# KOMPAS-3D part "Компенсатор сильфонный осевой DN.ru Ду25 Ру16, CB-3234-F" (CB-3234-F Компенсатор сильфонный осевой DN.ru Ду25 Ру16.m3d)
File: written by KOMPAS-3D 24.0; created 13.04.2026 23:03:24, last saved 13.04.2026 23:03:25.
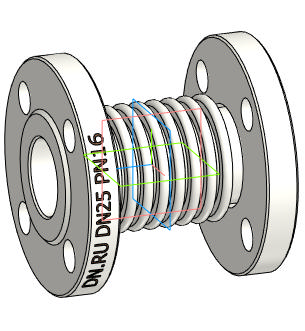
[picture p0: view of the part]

Document properties: Автор: DN.RU; Полное имя файла: D:\PROJECT CAD\DN.RU\...198(ACTUALE). CB-3234-F Компенсатор сильфонный осевой DN.ru\Исходники\DN25\CB-3234-F Компенсатор сильфонный осевой DN.ru Ду25 Ру16.m3d

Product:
- Body: Твердое тело1  | qty 1
    Масса: 2.406826
- Part/product: Компенсатор сильфонный осевой DN.ru Ду25 Ру16  | designation CB-3234-F
    Масса: 2.7
    Раздел спецификации: Прочие изделия
    Комментарий: D140-02110
    Примечание: D140-02110
    additional columns: Типовые

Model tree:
1. Твердое тело1  (labels: Твердое тело1)

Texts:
  CB-3234-F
